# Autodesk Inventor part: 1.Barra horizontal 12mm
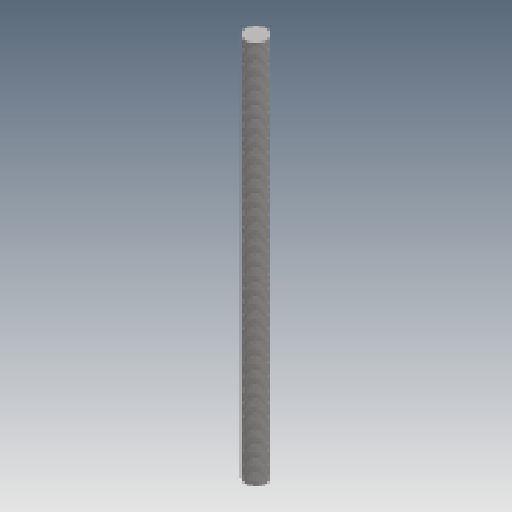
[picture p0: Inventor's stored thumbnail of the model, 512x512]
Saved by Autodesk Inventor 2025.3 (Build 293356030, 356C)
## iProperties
Created: 2025-10
Part Number: 1.Barra horizontal 12mm
Material: Hierro, fundido
Document SubType Name: Modeling
Designer: User
Density: 7.15 g/cm^3
Appearance: Inoxidable - Bruñido
Author: User
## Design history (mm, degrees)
sketch "Boceto1"
  geometry: C1 r 6 at (0, 0); 1 further point
  constraints: 1 centre point
  dimensions: "d0" = 0 distance of point (0, 0) C1.centre; "d1" = 0 distance of C1.centre point (0, 0); "d2" = 12 diameter of C1
extrude "Extrusión1" new body sketch "Boceto1" stored distance "d3" = 220; taper "d4" = 0 deg
feature "Rosca1" dims "d5" = 200, "d6" = 0
node "Sólido1"
node "Acabados"
node "Finish1" dims "Finish1_Area" = 851.99993
